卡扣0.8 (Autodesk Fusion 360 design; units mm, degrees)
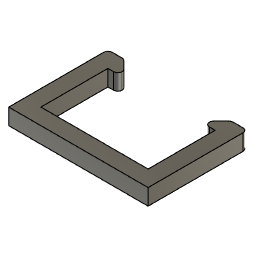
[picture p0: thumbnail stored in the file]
sketch "草图1" plane through (0, 0, 0) normal (0, 0, 1) x axis (1, 0, 0)
  line L1 (13, 9.25) -> (-13, 9.25)
  line L2 (13, -9.25) -> (13, 9.25)
  line L3 (-13, -9.25) -> (13, -9.25)
  line L4 (-13, 9.25) -> (-13, -9.25)
  line L5 (13, -9.25) -> (-13, 9.25)
  line L6 (-13, -9.25) -> (13, 9.25)
  line L7 (10, 6.25) -> (-10, 6.25)
  line L8 (10, -6.25) -> (10, 6.25)
  line L9 (-10, -6.25) -> (10, -6.25)
  line L10 (-10, 6.25) -> (-10, -6.25)
  line L11 (10, -6.25) -> (-10, 6.25)
  line L12 (-10, -6.25) -> (10, 6.25)
  point P6 (0, 0)
  point P1 (0, 0)
  point P11 (0, 0)
  point P4 (13, -9.25)
  point P5 (-13, -9.25)
  horizontal L1
  perpendicular L1 L2
  parallel L1 L3
  parallel L2 L4
  coincident L5 P6
  coincident L6 P6
  coincident P1 P6
  horizontal L7
  perpendicular L7 L8
  parallel L7 L9
  parallel L8 L10
  coincident L11 P11
  coincident L12 P11
  coincident P1 P11
  dimension "d1" distance P4 P5 = 26
  dimension "d2" distance L1 L3 = 18.5
  dimension "d3" distance L8 L10 = 20
  dimension "d4" distance L7 L9 = 12.5
extrude "拉伸1" new body sketch "草图1" profile of L1 L2 L3 L4 L7 L8 L9 L10 along normal blind 3
sketch "草图2" plane through (0, 0, 3) normal (0, 0, 1) x axis (-1, 0, 0)
  line L1 (10, 6.25) -> (-10, 6.25)
  line L2 (10, -6.25) -> (10, 6.25)
  line L3 (-10, -6.25) -> (10, -6.25)
  line L4 (-10, 6.25) -> (-10, -6.25)
  line L5 (-13, 9.25) -> (13, 9.25)
  line L6 (-13, -9.25) -> (-13, 9.25)
  line L7 (13, -9.25) -> (-13, -9.25)
  line L8 (13, 9.25) -> (13, -9.25)
  line L9 (-10.0005, -9.25) -> (-7, -6.25)
  line L10 (10.0253, -9.25) -> (7.0247, -6.25)
  point P10 (-7, -6.25)
  point P11 (-10.0005, -9.25)
  coincident L3 P10
  coincident L7 P11
  dimension "d7" distance L4 P10 = 3
extrude "拉伸2" cut sketch "草图2" profile of L3 L7 L9 L10 against normal blind 6
fillet "圆角" radius 0.8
